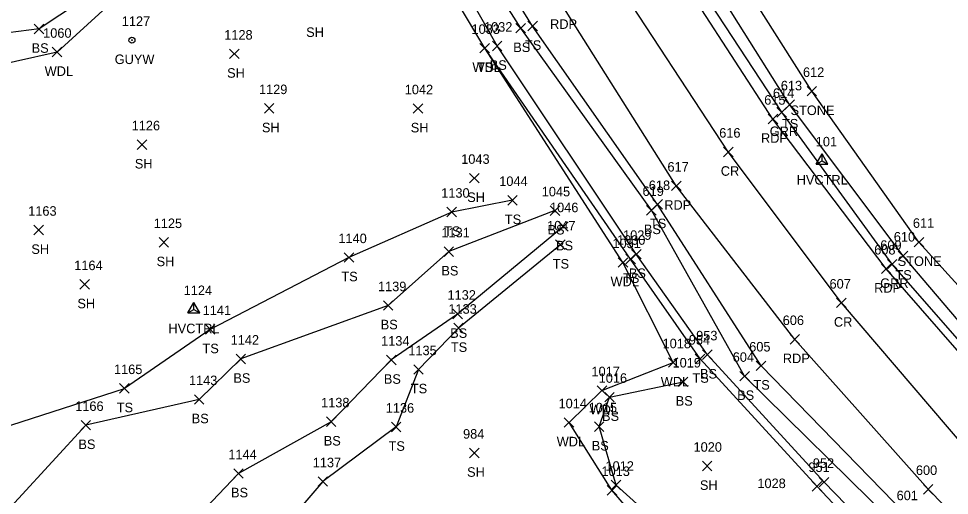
# Model space of a CAD drawing. Extents: x 1879695 to 1880991, y 836466 to 845172.
# Drawn here: x 1879796.4 to 1879991.4, y 844275.8 to 844375.9 of the extents above; entities that cross this region are included whole.
import ezdxf

# ---------------------------------------------------------------- set-up
doc = ezdxf.new("R2010")
doc.units = 0
for name, color, linetype in [('C_A', 7, 'Continuous'), ('C_I', 7, 'Continuous'), ('CPSM', 7, 'Continuous'), ('L_A', 7, 'Continuous'), ('L_I', 7, 'Continuous'), ('L_TIC', 7, 'Continuous'), ('LASF', 7, 'Continuous'), ('LAWA', 7, 'Continuous'), ('LELB', 7, 'Continuous'), ('P_A', 7, 'Continuous'), ('P_I', 7, 'Continuous'), ('P_TIC', 7, 'Continuous'), ('PET', 7, 'Continuous'), ('PRC', 7, 'Continuous'), ('R_A', 7, 'Continuous'), ('R_I', 7, 'Continuous'), ('R_TIC', 7, 'Continuous'), ('RGR', 7, 'Continuous'), ('U_A', 7, 'Continuous'), ('U_I', 7, 'Continuous'), ('UPGW', 7, 'Continuous')]:
    doc.layers.add(name, color=color, linetype=linetype)

msp = doc.modelspace()

# ---------------------------------------------------------------- linework, layer by layer
at = {"layer": 'CPSM'}
for p, q in [((1879963.49, 844345.35), (1879964.74, 844347.51)), ((1879965.99, 844345.35), (1879964.74, 844347.51)), ((1879964.74, 844346.07), (1879964.74, 844347.51)), ((1879963.49, 844345.35), (1879964.74, 844346.07)), ((1879963.49, 844345.35), (1879965.99, 844345.35)), ((1879964.74, 844346.07), (1879964.74, 844346.07)), ((1879964.74, 844346.07), (1879965.99, 844345.35)), ((1879831.83, 844314.15), (1879833.08, 844316.31)), ((1879834.33, 844314.15), (1879833.08, 844316.31)), ((1879833.08, 844314.87), (1879833.08, 844316.31)), ((1879831.83, 844314.15), (1879833.08, 844314.87)), ((1879831.83, 844314.15), (1879834.33, 844314.15)), ((1879833.08, 844314.87), (1879833.08, 844314.87)), ((1879833.08, 844314.87), (1879834.33, 844314.15))]:
    msp.add_line(p, q, dxfattribs=at)
at = {"layer": 'L_TIC'}
for points in [[(1879799.66, 844372.71), (1879801.66, 844374.71)], [(1879801.66, 844372.71), (1879799.66, 844374.71)], [(1879900.59, 844372.87), (1879902.59, 844374.87)], [(1879902.59, 844372.87), (1879900.59, 844374.87)], [(1879903.08, 844373.32), (1879905.08, 844375.32)], [(1879905.08, 844373.32), (1879903.08, 844375.32)], [(1879893.06, 844368.68), (1879895.06, 844370.68)], [(1879895.06, 844368.68), (1879893.06, 844370.68)], [(1879893.06, 844368.68), (1879895.06, 844370.68)], [(1879895.06, 844368.68), (1879893.06, 844370.68)], [(1879895.67, 844369.14), (1879897.67, 844371.14)], [(1879897.67, 844369.14), (1879895.67, 844371.14)], [(1879803.42, 844367.86), (1879805.42, 844369.86)], [(1879805.42, 844367.86), (1879803.42, 844369.86)], [(1879840.58, 844367.48), (1879842.58, 844369.48)], [(1879842.58, 844367.48), (1879840.58, 844369.48)], [(1879961.59, 844359.65), (1879963.59, 844361.65)], [(1879963.59, 844359.65), (1879961.59, 844361.65)], [(1879956.94, 844356.83), (1879958.94, 844358.83)], [(1879958.94, 844356.83), (1879956.94, 844358.83)], [(1879847.87, 844356.04), (1879849.87, 844358.04)], [(1879849.87, 844356.04), (1879847.87, 844358.04)], [(1879879.06, 844356.01), (1879881.06, 844358.01)], [(1879881.06, 844356.01), (1879879.06, 844358.01)], [(1879821.24, 844348.44), (1879823.24, 844350.44)], [(1879823.24, 844348.44), (1879821.24, 844350.44)], [(1879890.89, 844341.41), (1879892.89, 844343.41)], [(1879892.89, 844341.41), (1879890.89, 844343.41)], [(1879898.86, 844336.77), (1879900.86, 844338.77)], [(1879900.86, 844336.77), (1879898.86, 844338.77)], [(1879929.28, 844335.91), (1879931.28, 844337.91)], [(1879931.28, 844335.91), (1879929.28, 844337.91)], [(1879886.14, 844334.3), (1879888.14, 844336.3)], [(1879888.14, 844334.3), (1879886.14, 844336.3)], [(1879907.77, 844334.59), (1879909.77, 844336.59)], [(1879909.77, 844334.59), (1879907.77, 844336.59)], [(1879927.97, 844334.67), (1879929.97, 844336.67)], [(1879929.97, 844334.67), (1879927.97, 844336.67)], [(1879909.55, 844331.26), (1879911.55, 844333.26)], [(1879911.55, 844331.26), (1879909.55, 844333.26)], [(1879799.55, 844330.52), (1879801.55, 844332.52)], [(1879801.55, 844330.52), (1879799.55, 844332.52)], [(1879825.81, 844327.94), (1879827.81, 844329.94)], [(1879827.81, 844327.94), (1879825.81, 844329.94)], [(1879908.9, 844327.44), (1879910.9, 844329.44)], [(1879910.9, 844327.44), (1879908.9, 844329.44)], [(1879984.05, 844327.99), (1879986.05, 844329.99)], [(1879986.05, 844327.99), (1879984.05, 844329.99)], [(1879885.53, 844325.99), (1879887.53, 844327.99)], [(1879887.53, 844325.99), (1879885.53, 844327.99)], [(1879924.82, 844325.46), (1879926.82, 844327.46)], [(1879926.82, 844325.46), (1879924.82, 844327.46)], [(1879980.71, 844325.11), (1879982.71, 844327.11)], [(1879982.71, 844325.11), (1879980.71, 844327.11)], [(1879864.6, 844324.77), (1879866.6, 844326.77)], [(1879866.6, 844324.77), (1879864.6, 844326.77)], [(1879922.02, 844323.72), (1879924.02, 844325.72)], [(1879924.02, 844323.72), (1879922.02, 844325.72)], [(1879923.63, 844324.43), (1879925.63, 844326.43)], [(1879925.63, 844324.43), (1879923.63, 844326.43)], [(1879809.2, 844319.11), (1879811.2, 844321.11)], [(1879811.2, 844319.11), (1879809.2, 844321.11)], [(1879872.81, 844314.69), (1879874.81, 844316.69)], [(1879874.81, 844314.69), (1879872.81, 844316.69)], [(1879887.37, 844312.9), (1879889.37, 844314.9)], [(1879889.37, 844312.9), (1879887.37, 844314.9)], [(1879835.5, 844309.68), (1879837.5, 844311.68)], [(1879837.5, 844309.68), (1879835.5, 844311.68)], [(1879887.55, 844309.96), (1879889.55, 844311.96)], [(1879889.55, 844309.96), (1879887.55, 844311.96)], [(1879939.72, 844304.37), (1879941.72, 844306.37)], [(1879941.72, 844304.37), (1879939.72, 844306.37)], [(1879841.94, 844303.47), (1879843.94, 844305.47)], [(1879843.94, 844303.47), (1879841.94, 844305.47)], [(1879873.46, 844303.26), (1879875.46, 844305.26)], [(1879875.46, 844303.26), (1879873.46, 844305.26)], [(1879932.53, 844302.72), (1879934.53, 844304.72)], [(1879934.53, 844302.72), (1879932.53, 844304.72)], [(1879938.18, 844303.48), (1879940.18, 844305.48)], [(1879940.18, 844303.48), (1879938.18, 844305.48)], [(1879950.96, 844302.04), (1879952.96, 844304.04)], [(1879952.96, 844302.04), (1879950.96, 844304.04)], [(1879879.16, 844301.26), (1879881.16, 844303.26)], [(1879881.16, 844301.26), (1879879.16, 844303.26)], [(1879947.51, 844299.87), (1879949.51, 844301.87)], [(1879949.51, 844299.87), (1879947.51, 844301.87)], [(1879934.63, 844298.68), (1879936.63, 844300.68)], [(1879936.63, 844298.68), (1879934.63, 844300.68)], [(1879817.53, 844297.3), (1879819.53, 844299.3)], [(1879819.53, 844297.3), (1879817.53, 844299.3)], [(1879817.53, 844297.3), (1879819.53, 844299.3)], [(1879819.53, 844297.3), (1879817.53, 844299.3)], [(1879917.62, 844296.85), (1879919.62, 844298.85)], [(1879919.62, 844296.85), (1879917.62, 844298.85)], [(1879833.2, 844294.98), (1879835.2, 844296.98)], [(1879835.2, 844294.98), (1879833.2, 844296.98)], [(1879919.19, 844295.47), (1879921.19, 844297.47)], [(1879921.19, 844295.47), (1879919.19, 844297.47)], [(1879860.88, 844290.31), (1879862.88, 844292.31)], [(1879862.88, 844290.31), (1879860.88, 844292.31)], [(1879910.73, 844290.14), (1879912.73, 844292.14)], [(1879912.73, 844290.14), (1879910.73, 844292.14)], [(1879809.46, 844289.57), (1879811.46, 844291.57)], [(1879811.46, 844289.57), (1879809.46, 844291.57)], [(1879809.46, 844289.57), (1879811.46, 844291.57)], [(1879811.46, 844289.57), (1879809.46, 844291.57)], [(1879874.49, 844289.2), (1879876.49, 844291.2)], [(1879876.49, 844289.2), (1879874.49, 844291.2)], [(1879917.04, 844289.27), (1879919.04, 844291.27)], [(1879919.04, 844289.27), (1879917.04, 844291.27)], [(1879890.87, 844283.75), (1879892.87, 844285.75)], [(1879892.87, 844283.75), (1879890.87, 844285.75)], [(1879939.67, 844281), (1879941.67, 844283)], [(1879941.67, 844281), (1879939.67, 844283)], [(1879841.44, 844279.44), (1879843.44, 844281.44)], [(1879843.44, 844279.44), (1879841.44, 844281.44)], [(1879859.13, 844277.75), (1879861.13, 844279.75)], [(1879861.13, 844277.75), (1879859.13, 844279.75)], [(1879920.57, 844277.01), (1879922.57, 844279.01)], [(1879922.57, 844277.01), (1879920.57, 844279.01)], [(1879962.67, 844276.76), (1879964.67, 844278.76)], [(1879964.67, 844276.76), (1879962.67, 844278.76)], [(1879964.17, 844277.62), (1879966.17, 844279.62)], [(1879966.17, 844277.62), (1879964.17, 844279.62)], [(1879919.72, 844275.91), (1879921.72, 844277.91)], [(1879921.72, 844275.91), (1879919.72, 844277.91)]]:
    msp.add_lwpolyline(points, dxfattribs=at)
at = {"layer": 'LASF'}
msp.add_lwpolyline([(1880139.87, 844182.06), (1880107.81, 844210.08), (1880073.67, 844241.21), (1880039.73, 844270.44), (1880011.8, 844299.45), (1879985.05, 844328.99), (1879962.59, 844360.65), (1879939.31, 844397.46), (1879924.45, 844424.63), (1879917.02, 844424.23), (1879898.51, 844460.46), (1879892.86, 844475.33), (1879896.16, 844478.29), (1879889.96, 844497.62)], dxfattribs=at)
at = {"layer": 'LAWA'}
for points in [[(1879928.58, 844267.77), (1879920.72, 844276.91), (1879911.73, 844291.14), (1879918.62, 844297.85), (1879933.53, 844303.72), (1879923.02, 844324.72), (1879894.06, 844369.68), (1879882.81, 844388.57)], [(1879819.57, 844382.71), (1879804.42, 844368.86), (1879778.2, 844362.97), (1879757.09, 844354), (1879744.7, 844348.18), (1879765.14, 844329.69), (1879767.09, 844328.18), (1879751.53, 844316.81), (1879725.54, 844311.2), (1879721.03, 844324.7), (1879721.87, 844351.94), (1879722.01, 844368.7), (1879730.25, 844377.49)]]:
    msp.add_lwpolyline(points, dxfattribs=at)
at = {"layer": 'LELB'}
for points in [[(1880237.65, 844030.17), (1880225.55, 844045.25), (1880203.19, 844067.94), (1880175.04, 844095.38), (1880141.55, 844124.24), (1880111.59, 844152.12), (1880079.67, 844179.09), (1880044.89, 844208.16), (1880013.5, 844237.54), (1880003.34, 844247.82), (1879979.16, 844270.62), (1879948.51, 844300.87), (1879928.97, 844335.67), (1879901.59, 844373.87), (1879881.39, 844405.75), (1879863.37, 844445.07), (1879846.41, 844479.41), (1879833.35, 844517.23), (1879821, 844560.9), (1879811.24, 844600.26), (1879800.64, 844646.71), (1879794.2, 844680.16), (1879792.03, 844683.6), (1879789.08, 844683.63)], [(1880243.53, 844023.94), (1880226.64, 844046.28), (1880204.68, 844069.12), (1880177.19, 844097.39), (1880144.15, 844127.37), (1880114.34, 844154.46), (1880082.65, 844181.38), (1880047.53, 844211.78), (1880015.32, 844240.12), (1879982.29, 844271.84), (1879951.96, 844303.04), (1879930.28, 844336.91), (1879904.08, 844374.32), (1879883.92, 844406.9), (1879866.98, 844446.02), (1879852.23, 844482.49), (1879838.68, 844519.35), (1879826.86, 844562.48), (1879815.22, 844600.52)], [(1880274.18, 844042.18), (1880252.69, 844068.34), (1880228.42, 844092.99), (1880199.77, 844120.37), (1880165.71, 844151.73), (1880135.43, 844177.69), (1880104.5, 844206.3), (1880070.17, 844236.88), (1880037.83, 844267.79), (1880007.31, 844296.06), (1879981.71, 844326.11), (1879957.94, 844357.83), (1879934.98, 844394.4), (1879917.02, 844424.23)], [(1880002.51, 844242.73), (1879985.64, 844257.52), (1879965.17, 844278.62), (1879940.72, 844305.37), (1879925.82, 844326.46), (1879896.67, 844370.14), (1879885.64, 844389.62), (1879876.9, 844403.13), (1879868.08, 844418.79), (1879858.9, 844415.1), (1879849.52, 844405.96), (1879835.24, 844394.65), (1879817.98, 844385.29), (1879800.66, 844373.71), (1879774.59, 844370.4), (1879756.19, 844355.96), (1879741.66, 844350.26)], [(1880061.24, 844186.41), (1880044.41, 844199.51), (1880029.44, 844214.36), (1880014.82, 844229.08), (1880001.48, 844240.9), (1879983.99, 844256.18), (1879963.67, 844277.76), (1879939.18, 844304.48), (1879924.63, 844325.43), (1879894.06, 844369.68)], [(1879899.86, 844337.77), (1879887.14, 844335.3), (1879865.6, 844325.77), (1879836.5, 844310.68), (1879818.53, 844298.3)], [(1879908.77, 844335.59), (1879886.53, 844326.99), (1879873.81, 844315.69), (1879842.94, 844304.47), (1879834.2, 844295.98), (1879810.46, 844290.57)], [(1879910.55, 844332.26), (1879888.37, 844313.9), (1879874.46, 844304.26), (1879861.88, 844291.31), (1879842.44, 844280.44), (1879809.17, 844245.49)], [(1879909.9, 844328.44), (1879888.55, 844310.96), (1879880.16, 844302.26), (1879875.49, 844290.2), (1879860.13, 844278.75), (1879847.54, 844264.1), (1879819.41, 844238.78)], [(1879779.75, 844285.77), (1879818.53, 844298.3)], [(1879929.51, 844266.2), (1879930.96, 844269.54), (1879921.57, 844278.01), (1879918.04, 844290.27), (1879920.19, 844296.47), (1879935.63, 844299.68)], [(1879856.87, 844231.08), (1879838.42, 844207.88), (1879818.44, 844213.69), (1879819.41, 844238.78), (1879809.17, 844245.49), (1879789.24, 844267.52), (1879810.46, 844290.57)]]:
    msp.add_lwpolyline(points, dxfattribs=at)
at = {"layer": 'P_TIC'}
for points in [[(1879953.46, 844353.82), (1879955.46, 844355.82)], [(1879955.46, 844353.82), (1879953.46, 844355.82)], [(1879944.09, 844346.91), (1879946.09, 844348.91)], [(1879946.09, 844346.91), (1879944.09, 844348.91)], [(1879933.2, 844339.79), (1879935.2, 844341.79)], [(1879935.2, 844339.79), (1879933.2, 844341.79)], [(1879977.17, 844322.39), (1879979.17, 844324.39)], [(1879979.17, 844322.39), (1879977.17, 844324.39)], [(1879967.79, 844315.24), (1879969.79, 844317.24)], [(1879969.79, 844315.24), (1879967.79, 844317.24)], [(1879958.04, 844307.59), (1879960.04, 844309.59)], [(1879960.04, 844307.59), (1879958.04, 844309.59)], [(1879985.99, 844276.13), (1879987.99, 844278.13)], [(1879987.99, 844276.13), (1879985.99, 844278.13)]]:
    msp.add_lwpolyline(points, dxfattribs=at)
at = {"layer": 'PET'}
for points in [[(1880269.75, 844039.67), (1880250.27, 844065.9), (1880225.97, 844090.31), (1880195.98, 844117.55), (1880162.1, 844148.13), (1880132.62, 844174.7), (1880101.36, 844203.03), (1880066.94, 844232.59), (1880034.5, 844263.16), (1880004.09, 844293.64), (1879978.17, 844323.39), (1879954.46, 844354.82), (1879930.76, 844391.37), (1879912.37, 844423.12), (1879894.17, 844458.9), (1879879.41, 844492.34), (1879865.46, 844529.81), (1879852.88, 844569.32), (1879843.17, 844608.03)], [(1880246.17, 844024.86), (1880229.35, 844048.54), (1880207.67, 844072.23), (1880179.65, 844099.99), (1880146.48, 844130.19), (1880116.3, 844156.76), (1880085.61, 844184.86), (1880050.42, 844215.32), (1880017.65, 844245.83), (1879986.99, 844277.13), (1879959.04, 844308.59), (1879934.2, 844340.79), (1879910.26, 844378.73), (1879891.14, 844411.43), (1879872.36, 844448.44), (1879856.33, 844484.43), (1879842.37, 844521.56), (1879829.6, 844563.28), (1879820.43, 844602.23)]]:
    msp.add_lwpolyline(points, dxfattribs=at)
at = {"layer": 'PRC'}
msp.add_lwpolyline([(1880256.85, 844032.04), (1880238.91, 844056.2), (1880216.7, 844080.65), (1880187.27, 844108.93), (1880154.23, 844138.82), (1880124.19, 844165.48), (1880092.74, 844193.41), (1880058.56, 844223.39), (1880025.99, 844253.92), (1879995.14, 844285.41), (1879968.79, 844316.24), (1879945.09, 844347.91), (1879920.67, 844385.19), (1879902.45, 844417.14), (1879883.72, 844454.21), (1879868.53, 844488.38), (1879854.47, 844526.01), (1879841.81, 844566.38), (1879832.13, 844605)], dxfattribs=at)
at = {"layer": 'R_TIC'}
for points in [[(1879955.29, 844355.24), (1879957.29, 844357.24)], [(1879957.29, 844355.24), (1879955.29, 844357.24)], [(1879978.45, 844323.37), (1879980.45, 844325.37)], [(1879980.45, 844323.37), (1879978.45, 844325.37)]]:
    msp.add_lwpolyline(points, dxfattribs=at)
at = {"layer": 'RGR'}
msp.add_lwpolyline([(1880270.9, 844040.93), (1880251.09, 844066.69), (1880226.93, 844091.38), (1880197.34, 844118.12), (1880162.87, 844149.15), (1880133.45, 844175.62), (1880101.92, 844203.72), (1880067.67, 844234.21), (1880035.3, 844264.37), (1880005.3, 844294.8), (1879979.45, 844324.37), (1879956.29, 844356.24), (1879932.57, 844392.56), (1879914.54, 844423.96), (1879896.38, 844459.86), (1879881.66, 844493.03), (1879867.6, 844530.61), (1879855.21, 844570.01), (1879845.36, 844608.98)], dxfattribs=at)
at = {"layer": 'UPGW'}
for radius in [0.625, 0.0833]:
    msp.add_circle((1879820.12, 844371.35), radius, dxfattribs=at)

# ---------------------------------------------------------------- texts
at = {"layer": 'C_A'}
for p in [(1879959.43, 844341.07), (1879827.77, 844309.87)]:
    msp.add_text('HVCTRL', height=2, dxfattribs=at).set_placement(p)
at = {"layer": 'C_I'}
for s, p in [('101', (1879963.43, 844349.07)), ('1124', (1879830.96, 844317.87))]:
    msp.add_text(s, height=2, dxfattribs=at).set_placement(p)
at = {"layer": 'L_A'}
for s, p in [('SH', (1879856.63, 844372.04)), ('BS', (1879799.1, 844368.71)), ('BS', (1879900.03, 844368.87)), ('TS', (1879902.49, 844369.32)), ('WDL', (1879891.47, 844364.68)), ('TS', (1879892.46, 844364.68)), ('BS', (1879895.11, 844365.14)), ('WDL', (1879801.83, 844363.86)), ('SH', (1879840.07, 844363.48)), ('STONE', (1879958.14, 844355.65)), ('TS', (1879956.35, 844352.83)), ('SH', (1879847.36, 844352.04)), ('SH', (1879878.55, 844352.01)), ('SH', (1879820.72, 844344.44)), ('SH', (1879890.38, 844337.41)), ('TS', (1879898.27, 844332.77)), ('TS', (1879928.69, 844331.91)), ('TS', (1879885.55, 844330.3)), ('BS', (1879907.21, 844330.59)), ('BS', (1879927.41, 844330.67)), ('BS', (1879908.99, 844327.26)), ('SH', (1879799.04, 844326.52)), ('SH', (1879825.29, 844323.94)), ('TS', (1879908.31, 844323.44)), ('STONE', (1879980.6, 844323.99)), ('BS', (1879884.97, 844321.99)), ('BS', (1879924.26, 844321.46)), ('TS', (1879980.12, 844321.11)), ('TS', (1879864.01, 844320.77)), ('WDL', (1879920.43, 844319.72)), ('TS', (1879923.04, 844320.43)), ('SH', (1879808.69, 844315.11)), ('BS', (1879872.25, 844310.69)), ('BS', (1879886.81, 844308.9)), ('TS', (1879834.91, 844305.68)), ('TS', (1879886.96, 844305.96)), ('BS', (1879939.16, 844300.37)), ('BS', (1879841.38, 844299.47)), ('BS', (1879872.91, 844299.26)), ('WDL', (1879930.94, 844298.72)), ('TS', (1879937.59, 844299.48)), ('TS', (1879950.37, 844298.04)), ('TS', (1879878.57, 844297.26)), ('BS', (1879946.95, 844295.87)), ('BS', (1879934.07, 844294.68)), ('TS', (1879816.94, 844293.3)), ('TS', (1879816.94, 844293.3)), ('WDL', (1879916.04, 844292.85)), ('BS', (1879832.64, 844290.98)), ('BS', (1879918.63, 844291.47)), ('BS', (1879860.32, 844286.31)), ('WDL', (1879909.14, 844286.14)), ('BS', (1879808.9, 844285.57)), ('BS', (1879808.9, 844285.57)), ('TS', (1879873.9, 844285.2)), ('BS', (1879916.48, 844285.27)), ('SH', (1879890.36, 844279.75)), ('SH', (1879939.15, 844277)), ('BS', (1879840.88, 844275.44))]:
    msp.add_text(s, height=2, dxfattribs=at).set_placement(p)
at = {"layer": 'L_I'}
for s, p in [('1060', (1879801.51, 844371.86)), ('1033', (1879891.28, 844372.68)), ('1033', (1879891.28, 844372.68)), ('1032', (1879893.9, 844373.14)), ('1128', (1879839.46, 844371.48)), ('612', (1879960.75, 844363.65)), ('613', (1879956.1, 844360.83)), ('1129', (1879846.74, 844360.04)), ('1042', (1879877.29, 844360.01)), ('1126', (1879820.06, 844352.44)), ('1043', (1879889.12, 844345.41)), ('1044', (1879897.09, 844340.77)), ('619', (1879927.12, 844338.67)), ('618', (1879928.44, 844339.91)), ('1130', (1879884.93, 844338.3)), ('1045', (1879906, 844338.59)), ('1046', (1879907.73, 844335.26)), ('1163', (1879798.38, 844334.52)), ('1125', (1879824.68, 844331.94)), ('1047', (1879907.13, 844331.44)), ('611', (1879983.78, 844331.99)), ('1131', (1879884.97, 844329.99)), ('1029', (1879923.04, 844329.46)), ('610', (1879979.78, 844329.11)), ('1140', (1879863.38, 844328.77)), ('1031', (1879920.81, 844327.72)), ('1030', (1879921.77, 844328.43)), ('1164', (1879808.03, 844323.11)), ('1139', (1879871.68, 844318.69)), ('1132', (1879886.25, 844316.9)), ('1141', (1879834.94, 844313.68)), ('1133', (1879886.43, 844313.96)), ('1142', (1879840.81, 844307.47)), ('954', (1879936.82, 844307.48)), ('953', (1879938.36, 844308.37)), ('1134', (1879872.34, 844307.26)), ('1018', (1879931.32, 844306.72)), ('605', (1879949.48, 844306.04)), ('1135', (1879878.04, 844305.26)), ('604', (1879946.02, 844303.87)), ('1019', (1879933.41, 844302.68)), ('1165', (1879816.35, 844301.3)), ('1165', (1879816.35, 844301.3)), ('1017', (1879916.42, 844300.85)), ('1143', (1879832.07, 844298.98)), ('1016', (1879917.93, 844299.47)), ('1138', (1879859.76, 844294.31)), ('1014', (1879909.52, 844294.14)), ('1166', (1879808.23, 844293.57)), ('1166', (1879808.23, 844293.57)), ('1136', (1879873.31, 844293.2)), ('1015', (1879915.83, 844293.27)), ('984', (1879889.51, 844287.75)), ('1020', (1879937.81, 844285)), ('1144', (1879840.32, 844283.44)), ('1137', (1879858.01, 844281.75)), ('1012', (1879919.36, 844281.01)), ('951', (1879961.88, 844280.76)), ('952', (1879962.81, 844281.62)), ('1013', (1879918.52, 844279.91)), ('1028', (1879951.19, 844277.38)), ('1028', (1879951.19, 844277.38)), ('601', (1879980.37, 844274.84))]:
    msp.add_text(s, height=2, dxfattribs=at).set_placement(p)
at = {"layer": 'P_A'}
for s, p in [('RDP', (1879907.75, 844373.73)), ('RDP', (1879951.95, 844349.82)), ('CR', (1879943.52, 844342.91)), ('RDP', (1879931.68, 844335.79)), ('RDP', (1879975.66, 844318.39)), ('CR', (1879967.23, 844311.24)), ('RDP', (1879956.53, 844303.59))]:
    msp.add_text(s, height=2, dxfattribs=at).set_placement(p)
at = {"layer": 'P_I'}
for s, p in [('615', (1879952.62, 844357.82)), ('616', (1879943.19, 844350.91)), ('617', (1879932.35, 844343.79)), ('608', (1879975.68, 844326.39)), ('607', (1879966.31, 844319.24)), ('606', (1879956.5, 844311.59)), ('600', (1879984.41, 844280.13))]:
    msp.add_text(s, height=2, dxfattribs=at).set_placement(p)
at = {"layer": 'R_A'}
for p in [(1879953.78, 844351.24), (1879976.94, 844319.37)]:
    msp.add_text('GRR', height=2, dxfattribs=at).set_placement(p)
at = {"layer": 'R_I'}
for s, p in [('614', (1879954.45, 844359.24)), ('609', (1879976.95, 844327.37))]:
    msp.add_text(s, height=2, dxfattribs=at).set_placement(p)
at = {"layer": 'U_A'}
msp.add_text('GUYW', height=2, dxfattribs=at).set_placement((1879816.51, 844366.35))
at = {"layer": 'U_I'}
msp.add_text('1127', height=2, dxfattribs=at).set_placement((1879817.99, 844374.35))

doc.saveas('drawing.dxf')
